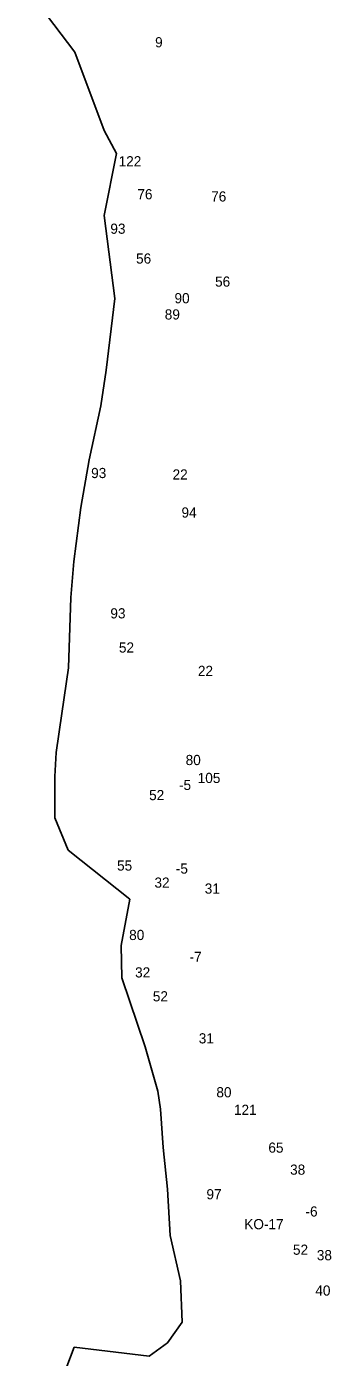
# Model space of a CAD drawing. Extents: x -782710 to -781421, y -973233 to -970222.
# Drawn here: x -782659 to -782487, y -972483 to -971729 of the extents above; entities that cross this region are included whole.
import ezdxf

# ---------------------------------------------------------------- set-up
doc = ezdxf.new("R2010")
doc.units = 0
doc.layers.add('Vrstva 13', color=7, linetype='Continuous')
doc.layers.add('Vrstva 24', color=7, linetype='Continuous')

msp = doc.modelspace()

# ---------------------------------------------------------------- linework, layer by layer
at = {"layer": 'Vrstva 13'}
for p, q in [((-782632.07, -971743.47), (-782659.3, -971707.4)), ((-782615.48, -971787.84), (-782632.07, -971743.47)), ((-782608.34, -971800.84), (-782615.48, -971787.84)), ((-782615.36, -971836.06), (-782608.34, -971800.84)), ((-782609.3, -971882.99), (-782615.36, -971836.06)), ((-782614.3, -971923.53), (-782609.3, -971882.99)), ((-782617.28, -971943.85), (-782614.3, -971923.53)), ((-782623.87, -971974.34), (-782617.28, -971943.85)), ((-782628.55, -972001.31), (-782623.87, -971974.34)), ((-782632.54, -972031.85), (-782628.55, -972001.31)), ((-782634.19, -972052.39), (-782632.54, -972031.85)), ((-782635.58, -972092.23), (-782634.19, -972052.39)), ((-782639.41, -972118.03), (-782635.58, -972092.23)), ((-782642.55, -972140.01), (-782639.41, -972118.03)), ((-782643.24, -972153.63), (-782642.55, -972140.01)), ((-782643.4, -972177.14), (-782643.24, -972153.63)), ((-782635.85, -972195.39), (-782643.4, -972177.14)), ((-782600.86, -972223.1), (-782635.85, -972195.39)), ((-782605.81, -972249.33), (-782600.86, -972223.1)), ((-782605.44, -972267.78), (-782605.81, -972249.33)), ((-782592.21, -972306.77), (-782605.44, -972267.78)), ((-782584.97, -972331.92), (-782592.21, -972306.77)), ((-782583.48, -972342.14), (-782584.97, -972331.92)), ((-782581.99, -972363.79), (-782583.48, -972342.14)), ((-782579.49, -972387.36), (-782581.99, -972363.79)), ((-782578, -972413.69), (-782579.49, -972387.36)), ((-782572.21, -972439.23), (-782578, -972413.69)), ((-782571.2, -972462.74), (-782572.21, -972439.23)), ((-782579.54, -972474.44), (-782571.2, -972462.74)), ((-782637.18, -972489.33), (-782632.45, -972476.83)), ((-782632.45, -972476.83), (-782589.91, -972481.94)), ((-782589.91, -972481.94), (-782579.54, -972474.44))]:
    msp.add_line(p, q, dxfattribs=at)

# ---------------------------------------------------------------- texts
at = {"layer": 'Vrstva 24'}
for s, p in [('9', (-782586.576, -971740.752)), ('122', (-782607.225, -971808.152)), ('76', (-782596.628, -971826.812)), ('76', (-782554.848, -971828.082)), ('93', (-782611.906, -971846.332)), ('56', (-782597.346, -971863.222)), ('56', (-782552.626, -971876.302)), ('90', (-782575.593, -971885.702)), ('89', (-782581.106, -971894.882)), ('93', (-782622.776, -971984.692)), ('22', (-782576.693, -971985.532)), ('94', (-782571.632, -972007.072)), ('93', (-782611.906, -972064.162)), ('52', (-782607.063, -972083.522)), ('22', (-782562.343, -972096.772)), ('80', (-782569.289, -972147.222)), ('105', (-782562.462, -972157.382)), ('-5', (-782573.05, -972161.34)), ('52', (-782589.973, -972167.092)), ('55', (-782608.113, -972206.972)), ('-5', (-782574.84, -972208.71)), ('32', (-782586.933, -972216.662)), ('31', (-782558.475, -972220.042)), ('80', (-782601.259, -972246.312)), ('-7', (-782567.062, -972258.71)), ('32', (-782597.903, -972267.512)), ('52', (-782587.863, -972281.052)), ('31', (-782561.855, -972304.862)), ('80', (-782551.889, -972335.382)), ('121', (-782541.948, -972345.342)), ('65', (-782522.456, -972366.752)), ('38', (-782510.143, -972379.212)), ('97', (-782557.508, -972393.142)), ('-6', (-782501.443, -972402.9)), ('KO-17', (-782536.096, -972410.09)), ('52', (-782508.543, -972424.552)), ('38', (-782495.023, -972427.632)), ('40', (-782495.875, -972447.672))]:
    msp.add_text(s, height=5.76, dxfattribs=at).set_placement(p)

doc.saveas('drawing.dxf')
